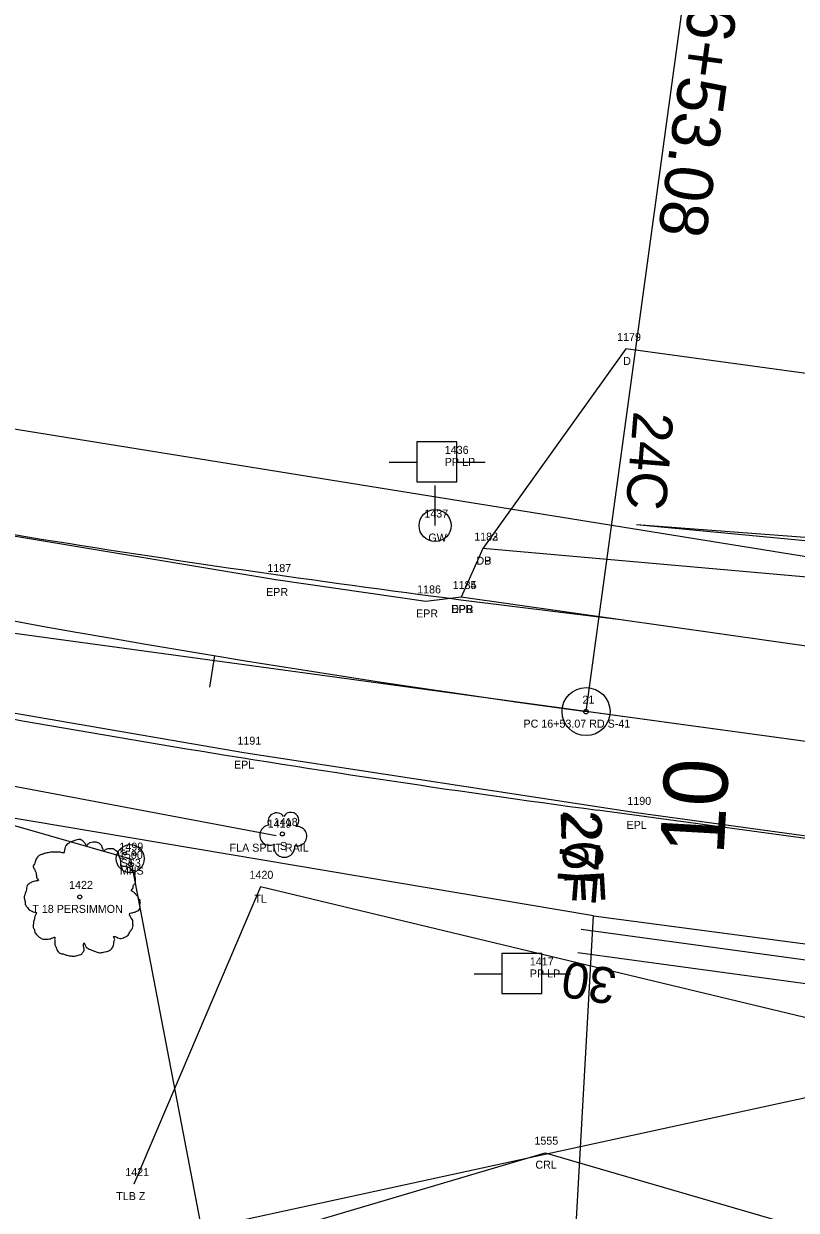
# Model space of a CAD drawing. Extents: x 1812113 to 1819860, y 1177395 to 1181185.
# Drawn here: x 1813468 to 1813564.5, y 1178709.1 to 1178857.4 of the extents above; entities that cross this region are included whole.
import ezdxf

# ---------------------------------------------------------------- set-up
doc = ezdxf.new("R2010")
doc.units = 0
for name, color, linetype in [('RD_EX_DR_Inlet', 7, 'Continuous'), ('RD_EX_Driveway', 7, 'Continuous'), ('RD_EX_Driveway_txCode', 7, 'Continuous'), ('RD_EX_DV_Prop', 7, 'Continuous'), ('RD_EX_Fence_Other', 7, 'Continuous'), ('RD_EX_Fence_Other_txCode', 7, 'Continuous'), ('RD_EX_H2O', 7, 'Continuous'), ('RD_EX_H2O_txCode', 7, 'Continuous'), ('RD_EX_Road', 7, 'Continuous'), ('RD_EX_Road_txCode', 7, 'Continuous'), ('RD_EX_RW', 7, 'Continuous'), ('RD_EX_UT', 7, 'Continuous'), ('RD_EX_UT_txCode', 7, 'Continuous'), ('RD_EX_VEG', 7, 'Continuous'), ('RD_EX_VEG_txCode', 7, 'Continuous'), ('RD_HC_CL', 7, 'Continuous'), ('RD_HC_Data', 7, 'Continuous'), ('RD_HC_Data_Tic', 7, 'Continuous'), ('RD_HC_TX_StaOther', 7, 'Continuous'), ('RD_HC_txCode', 7, 'Continuous'), ('RD_PD_ALT1_TrvlWay', 7, 'Continuous'), ('RD_PD_ALT3_LnLine', 7, 'Continuous'), ('RD_PD_CstnLmt', 7, 'Continuous'), ('RD_PD_PatLn1', 7, 'Continuous'), ('RD_SMD_Locator', 7, 'Continuous')]:
    doc.layers.add(name, color=color, linetype=linetype)

msp = doc.modelspace()

# ---------------------------------------------------------------- linework, layer by layer
at = {"layer": 'RD_EX_DR_Inlet'}
for centre, radius in [((1813481.28, 1178753.05), 1.75), ((1813480.62, 1178753.68), 0.175), ((1813481.84, 1178753.61), 0.175), ((1813481.19, 1178752.38), 0.175)]:
    msp.add_circle(centre, radius, dxfattribs=at)
at = {"layer": 'RD_EX_Driveway'}
for points in [[(1813613.34, 1178784.52), (1813617.78, 1178806.55), (1813543.17, 1178816.74), (1813525.31, 1178791.79)], [(1813638.42, 1178791.25), (1813630.13, 1178786.38), (1813613.34, 1178784.52), (1813588.43, 1178786.24), (1813525.31, 1178791.79), (1813522.62, 1178785.74)]]:
    msp.add_lwpolyline(points, dxfattribs=at)
at = {"layer": 'RD_EX_DV_Prop'}
msp.add_line((1813534.09, 1178656.72), (1813539.17, 1178745.92), dxfattribs=at)
at = {"layer": 'RD_EX_Fence_Other'}
msp.add_lwpolyline([(1813499.51, 1178755.92), (1813424.16, 1178770.12), (1813422.76, 1178764.09)], dxfattribs=at)
at = {"layer": 'RD_EX_H2O'}
msp.add_lwpolyline([(1813499.62, 1178706.37), (1813533.11, 1178716.31), (1813566.87, 1178706.45), (1813581.02, 1178703.79), (1813602.73, 1178697.66), (1813630.18, 1178688.94), (1813658.74, 1178690.22), (1813683.52, 1178690.56), (1813733.77, 1178695.63), (1813767.86, 1178725.16), (1813778.94, 1178729.95)], dxfattribs=at)
at = {"layer": 'RD_EX_Road'}
for p, q in [((1813499.47, 1178787.87), (1813450.56, 1178796.06)), ((1813518.21, 1178785.19), (1813499.47, 1178787.87)), ((1813522.62, 1178785.74), (1813518.21, 1178785.19)), ((1813596.09, 1178775.31), (1813522.62, 1178785.74))]:
    msp.add_line(p, q, dxfattribs=at)
msp.add_lwpolyline([(1813732.94, 1178707.95), (1813689.88, 1178731.75), (1813641.71, 1178744.36), (1813593.37, 1178752.09), (1813544.49, 1178758.77), (1813495.45, 1178766.29), (1813446.8, 1178774.66), (1813426.54, 1178777.95), (1813403.21, 1178782.55), (1813398.65, 1178783.84), (1813350.68, 1178796.09), (1813343.23, 1178797.92), (1813318.7, 1178804.23), (1813303.26, 1178808.85), (1813256.8, 1178823.17), (1813209.81, 1178838.91), (1813163.27, 1178855.57)], dxfattribs=at)
at = {"layer": 'RD_EX_RW'}
for p, q in [((1813632.03, 1178780.07), (1813400.47, 1178817.38)), ((1813539.17, 1178745.92), (1813409.98, 1178767.65)), ((1813539.17, 1178745.92), (1813638.67, 1178732.75))]:
    msp.add_line(p, q, dxfattribs=at)
at = {"layer": 'RD_EX_UT'}
for p, q in [((1813522.06, 1178805.14), (1813517.06, 1178805.14)), ((1813517.06, 1178805.14), (1813517.06, 1178800.14)), ((1813522.06, 1178800.14), (1813522.06, 1178805.14)), ((1813513.63, 1178802.58), (1813517.1, 1178802.58)), ((1813521.99, 1178802.58), (1813525.63, 1178802.58)), ((1813517.06, 1178800.14), (1813522.06, 1178800.14)), ((1813519.36, 1178794.67), (1813519.36, 1178799.67)), ((1813532.69, 1178741.21), (1813527.69, 1178741.21)), ((1813527.69, 1178741.21), (1813527.69, 1178736.21)), ((1813532.69, 1178736.21), (1813532.69, 1178741.21)), ((1813524.26, 1178738.65), (1813527.73, 1178738.65)), ((1813532.62, 1178738.65), (1813536.26, 1178738.65)), ((1813527.69, 1178736.21), (1813532.69, 1178736.21))]:
    msp.add_line(p, q, dxfattribs=at)
for points in [[(1812996.89, 1178919.95), (1813204.49, 1178832.44), (1813481.3, 1178753.03), (1813490.2, 1178706.76)], [(1813817.45, 1178777.9), (1813490.2, 1178706.76), (1813294.33, 1178669.42)]]:
    msp.add_lwpolyline(points, dxfattribs=at)
msp.add_circle((1813519.36, 1178794.67), 2, dxfattribs=at)
at = {"layer": 'RD_EX_VEG'}
msp.add_lwpolyline([(1813615.69, 1178721.17), (1813497.56, 1178749.53), (1813481.72, 1178712.39)], dxfattribs=at)
for centre, radius in [((1813500.28, 1178756.14), 0.25), ((1813474.98, 1178748.27), 0.25), ((1813474.97, 1178748.25), 0.0001)]:
    msp.add_circle(centre, radius, dxfattribs=at)
for centre, radius, start, end in [((1813499.56, 1178757.69), 1.08, 34.9763, 204.756), ((1813501.33, 1178757.84), 0.995, 308.7626, 152.0467), ((1813498.72, 1178755.98), 1.26, 96.4518, 294.734), ((1813502.12, 1178755.86), 1.22, 256.5667, 98.1046), ((1813500.53, 1178754.54), 1.32, 166.8827, 5.7589)]:
    msp.add_arc(centre, radius, start, end, dxfattribs=at)
for points in [[(1813475.11, 1178755.44), (1813474.81, 1178755.46), (1813474.49, 1178755.36), (1813474.24, 1178755.26), (1813474.02, 1178755.19), (1813473.79, 1178755.09), (1813473.49, 1178754.91), (1813473.27, 1178754.71), (1813473.14, 1178754.46), (1813473.09, 1178754.24), (1813473.04, 1178753.96), (1813473.04, 1178753.79), (1813472.92, 1178753.76), (1813472.77, 1178753.79), (1813472.52, 1178753.86), (1813472.27, 1178753.86), (1813472.02, 1178753.86), (1813471.67, 1178753.84), (1813471.32, 1178753.84), (1813471.04, 1178753.79), (1813470.72, 1178753.74), (1813470.34, 1178753.61), (1813469.99, 1178753.49), (1813469.69, 1178753.24), (1813469.44, 1178752.76), (1813469.32, 1178752.41), (1813469.17, 1178752.16), (1813469.32, 1178751.72), (1813469.49, 1178751.37), (1813469.52, 1178751.17), (1813469.59, 1178750.74), (1813469.69, 1178750.52), (1813469.82, 1178750.32), (1813469.74, 1178750.29), (1813469.37, 1178750.24), (1813469.07, 1178750.14), (1813468.64, 1178749.92), (1813468.42, 1178749.69), (1813468.32, 1178749.37), (1813468.29, 1178749.02), (1813468.19, 1178748.82), (1813468.12, 1178748.54), (1813468.09, 1178748.47), (1813468.04, 1178748.14), (1813468.14, 1178747.69), (1813468.17, 1178747.34), (1813468.29, 1178747.12), (1813468.44, 1178746.94), (1813468.62, 1178746.69), (1813469.02, 1178746.47), (1813469.34, 1178746.37), (1813469.54, 1178746.34), (1813469.37, 1178745.84), (1813469.32, 1178745.49), (1813469.19, 1178745.09), (1813469.19, 1178745.02), (1813469.14, 1178744.54), (1813469.29, 1178744.22), (1813469.37, 1178743.84), (1813469.54, 1178743.62), (1813469.82, 1178743.32), (1813470.14, 1178743.09), (1813470.64, 1178742.97), (1813471.04, 1178742.99), (1813471.62, 1178743.17), (1813471.87, 1178743.24), (1813471.84, 1178743.07), (1813471.87, 1178742.69), (1813471.87, 1178742.27), (1813472.02, 1178741.94), (1813472.12, 1178741.67), (1813472.27, 1178741.42), (1813472.59, 1178741.19), (1813472.99, 1178741.12), (1813473.42, 1178740.97), (1813473.87, 1178740.89), (1813474.36, 1178740.87), (1813474.96, 1178741.02), (1813475.24, 1178741.14), (1813475.34, 1178741.32), (1813475.54, 1178741.69), (1813475.49, 1178741.92), (1813475.51, 1178742.52), (1813475.61, 1178742.34), (1813475.79, 1178741.99), (1813476.29, 1178741.69), (1813476.69, 1178741.52), (1813477.16, 1178741.37), (1813477.46, 1178741.29), (1813477.94, 1178741.37), (1813478.31, 1178741.44), (1813478.69, 1178741.57), (1813478.99, 1178741.84), (1813479.16, 1178742.12), (1813479.21, 1178742.39), (1813479.29, 1178742.77), (1813479.34, 1178742.94)], [(1813479.34, 1178742.94), (1813479.26, 1178743.12), (1813479.21, 1178743.37), (1813479.29, 1178743.34), (1813479.46, 1178743.29), (1813479.74, 1178743.17), (1813479.96, 1178743.09), (1813480.29, 1178743.12), (1813480.56, 1178743.22), (1813481.01, 1178743.49), (1813481.29, 1178743.97), (1813481.56, 1178744.37), (1813481.64, 1178744.69), (1813481.59, 1178744.92), (1813481.56, 1178745.42), (1813481.36, 1178745.67), (1813481.31, 1178745.79), (1813481.21, 1178746.19), (1813481.29, 1178746.24), (1813481.56, 1178746.29), (1813481.94, 1178746.42), (1813482.21, 1178746.54), (1813482.44, 1178746.72), (1813482.51, 1178746.94), (1813482.49, 1178747.34), (1813482.54, 1178747.74), (1813482.46, 1178747.89), (1813482.36, 1178748.04), (1813482.29, 1178748.24), (1813482.14, 1178748.39), (1813482.04, 1178748.54), (1813481.94, 1178748.64), (1813481.81, 1178748.79), (1813481.64, 1178748.92), (1813481.49, 1178748.97), (1813481.44, 1178749.12), (1813481.59, 1178749.32), (1813481.64, 1178749.42), (1813481.66, 1178749.64), (1813481.89, 1178749.99), (1813481.94, 1178750.39), (1813481.89, 1178750.82), (1813481.84, 1178751.09), (1813481.69, 1178751.37), (1813481.49, 1178751.62), (1813481.36, 1178751.79), (1813481.19, 1178751.92), (1813480.86, 1178752.04), (1813480.61, 1178752.09), (1813480.26, 1178752.09), (1813480.06, 1178752.14), (1813480.09, 1178752.19), (1813480.09, 1178752.34), (1813480.09, 1178752.61), (1813480.01, 1178753.06), (1813479.86, 1178753.56), (1813479.86, 1178753.59), (1813479.76, 1178753.84), (1813479.54, 1178754.04), (1813479.36, 1178754.14), (1813479.16, 1178754.26), (1813478.91, 1178754.29), (1813478.61, 1178754.29), (1813478.34, 1178754.24), (1813478.14, 1178754.14), (1813477.96, 1178754.01), (1813477.89, 1178754.16), (1813477.79, 1178754.46), (1813477.74, 1178754.61), (1813477.59, 1178754.79), (1813477.36, 1178754.99), (1813476.91, 1178755.11), (1813476.29, 1178755.04), (1813475.99, 1178754.84), (1813475.84, 1178754.66), (1813475.79, 1178754.79), (1813475.59, 1178754.99), (1813475.49, 1178755.16), (1813475.31, 1178755.29), (1813475.16, 1178755.39), (1813475.06, 1178755.44)]]:
    msp.add_spline(points, degree=3, dxfattribs=at)
at = {"layer": 'RD_HC_CL'}
msp.add_line((1813641.28, 1178757.34), (1813538.22, 1178771.42), dxfattribs=at)
msp.add_arc((1813766.93, 1180445.18), 1689.31, 243.58271, 262.2191, dxfattribs=at)
at = {"layer": 'RD_HC_Data'}
msp.add_line((1813538.22, 1178771.42), (1813553.17, 1178880.85), dxfattribs=at)
for radius in [3, 0.282]:
    msp.add_circle((1813538.22, 1178771.42), radius, dxfattribs=at)
at = {"layer": 'RD_HC_Data_Tic'}
msp.add_line((1813491.82, 1178778.42), (1813491.17, 1178774.47), dxfattribs=at)
at = {"layer": 'RD_PD_ALT1_TrvlWay'}
msp.add_line((1813639.65, 1178745.45), (1813539.64, 1178759.11), dxfattribs=at)
for centre, radius, start, end in [((1813743.74, 1180497.85), 1726.67, 259.69377, 263.32028), ((1813772.51, 1180493.14), 1749.59, 258.72477, 262.35128)]:
    msp.add_arc(centre, radius, start, end, dxfattribs=at)
at = {"layer": 'RD_PD_ALT3_LnLine'}
for p, q in [((1813594.46, 1178790.99), (1813544.52, 1178794.78)), ((1813537.61, 1178744.25), (1813587.15, 1178737.48)), ((1813586.74, 1178734.51), (1813537.2, 1178741.28))]:
    msp.add_line(p, q, dxfattribs=at)
at = {"layer": 'RD_PD_CstnLmt'}
msp.add_line((1813594.33, 1178789.99), (1813544.52, 1178794.78), dxfattribs=at)
at = {"layer": 'RD_PD_PatLn1'}
msp.add_line((1813616.11, 1178760.78), (1813027.99, 1178841.14), dxfattribs=at)
at = {"layer": 'RD_SMD_Locator'}
for centre in [(1813543.17, 1178816.74), (1813525.31, 1178791.79), (1813525.31, 1178791.79), (1813499.47, 1178787.87), (1813522.62, 1178785.74), (1813522.62, 1178785.74), (1813518.21, 1178785.19), (1813538.22, 1178771.42), (1813495.45, 1178766.29), (1813544.49, 1178758.77), (1813499.51, 1178755.92), (1813481.3, 1178753.03), (1813497.56, 1178749.53), (1813533.11, 1178716.31), (1813481.72, 1178712.39)]:
    msp.add_circle(centre, 0.001, dxfattribs=at)

# ---------------------------------------------------------------- texts
at = {"layer": 'RD_EX_Driveway_txCode'}
for s, p in [('1179', (1813542.1, 1178817.74)), ('D', (1813542.86, 1178814.74)), ('1182', (1813524.25, 1178792.79)), ('1183', (1813524.25, 1178792.79)), ('DP', (1813524.53, 1178789.79)), ('DB', (1813524.53, 1178789.79)), ('1184', (1813521.56, 1178786.74)), ('DPB', (1813521.37, 1178783.74))]:
    msp.add_text(s, height=1, dxfattribs=at).set_placement(p)
at = {"layer": 'RD_EX_Fence_Other_txCode'}
for s, p in [('1419', (1813498.45, 1178756.92)), ('FLA SPLIT RAIL', (1813493.69, 1178753.92))]:
    msp.add_text(s, height=1, dxfattribs=at).set_placement(p)
at = {"layer": 'RD_EX_H2O_txCode'}
for s, p in [('1555', (1813531.77, 1178717.31)), ('CRL', (1813531.89, 1178714.31))]:
    msp.add_text(s, height=1, dxfattribs=at).set_placement(p)
at = {"layer": 'RD_EX_Road_txCode'}
for s, p in [('1187', (1813498.41, 1178788.87)), ('1186', (1813517.12, 1178786.19)), ('1185', (1813521.56, 1178786.74)), ('EPR', (1813498.25, 1178785.87)), ('EPR', (1813516.98, 1178783.19)), ('EPR', (1813521.39, 1178783.74)), ('1191', (1813494.67, 1178767.29)), ('EPL', (1813494.24, 1178764.29)), ('1190', (1813543.38, 1178759.77)), ('EPL', (1813543.28, 1178756.77))]:
    msp.add_text(s, height=1, dxfattribs=at).set_placement(p)
at = {"layer": 'RD_EX_UT_txCode'}
for s, p in [('1436', (1813520.57, 1178803.63)), ('PP LP', (1813520.57, 1178802.13)), ('1437', (1813518.02, 1178795.67)), ('GW', (1813518.52, 1178792.67)), ('1499', (1813479.93, 1178754.05)), ('1500', (1813479.87, 1178753.03)), ('SS3', (1813480.07, 1178752.03)), ('MHS', (1813479.99, 1178751.05)), ('1417', (1813531.2, 1178739.7)), ('PP LP', (1813531.2, 1178738.2))]:
    msp.add_text(s, height=1, dxfattribs=at).set_placement(p)
at = {"layer": 'RD_EX_VEG_txCode'}
for s, p in [('1418', (1813499.22, 1178757.14)), ('S', (1813499.98, 1178754.14)), ('1420', (1813496.18, 1178750.53)), ('1422', (1813473.64, 1178749.27)), ('TL', (1813496.79, 1178747.53)), ('T 18 PERSIMMON', (1813469.05, 1178746.27)), ('1421', (1813480.66, 1178713.39)), ('TLB Z', (1813479.53, 1178710.39))]:
    msp.add_text(s, height=1, dxfattribs=at).set_placement(p)
at = {"layer": 'RD_HC_Data'}
msp.add_text('PC=16+53.08', height=6, rotation=262.2191, dxfattribs=at).set_placement((1813553.9, 1178880.21))
at = {"layer": 'RD_HC_TX_StaOther'}
msp.add_text('10', height=8, rotation=86.7565, dxfattribs=at).set_placement((1813555.4, 1178753.44))
at = {"layer": 'RD_HC_txCode'}
for s, p in [('21', (1813537.77, 1178772.42)), ('PC 16+53.07 RD S-41', (1813530.4, 1178769.42))]:
    msp.add_text(s, height=1, dxfattribs=at).set_placement(p)
at = {"layer": 'RD_PD_ALT3_LnLine'}
for s, height, rotation, p in [('24C', 5, 265.3892, (1813544.17, 1178809.05)), ('27F', 5, 265.3892, (1813535.35, 1178759.16)), ('30', 4.5, 170.8507, (1813542.24, 1178739.22))]:
    msp.add_text(s, height=height, rotation=rotation, dxfattribs=at).set_placement(p)
at = {"layer": 'RD_PD_CstnLmt'}
msp.add_text('26F', height=5, rotation=273.2475, dxfattribs=at).set_placement((1813535.01, 1178758.9))

doc.saveas('drawing.dxf')
